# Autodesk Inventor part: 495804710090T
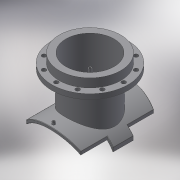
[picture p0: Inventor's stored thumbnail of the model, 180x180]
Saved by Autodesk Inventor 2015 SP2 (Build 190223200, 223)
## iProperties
Created: 2017-10
Part Number: 495804710090T
Material: Generic
Description: PLASSON FLANGED BRANCH SADDLE 450-800X100
Document SubType Name: Modeling
Designer: KIM
Density: 1 g/cm^3
Appearance: Default
Author: KIM
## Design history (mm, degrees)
derived "495904.ipt"
feature "Solid1::495904.ipt"
feature "Solid2::495904.ipt"
tag "TaggingFeature1"
body "Solid1"
other parameters: "d1" = 15, "d2" = 283.5, "d4" = 0, "d5" = 315, "d6" = 75, "d7" = 0, "d11" = 4, "d12" = 425.6, "d13" = 14, "d14" = 135, "d16" = 5 deg, "d18" = 4, "d19" = 14, "d20" = 0, "d21" = 3, "d22" = 0, "d23" = 525, "d36" = 135, "d38" = 0, "d39" = 2, "d42" = 158, "d44" = 88, "d46" = 126.4, "d47" = 16, "d48" = 10.4, "d49" = 77, "d51" = 816, "d53" = 0, "d54" = 18, "d57" = 0, "d59" = 360 deg, "d61" = 22, "d63" = 0, "d_1" = 158, "B_" = 315, "x_" = 15, "D_" = 16, "t_" = 22, "s_" = 18
